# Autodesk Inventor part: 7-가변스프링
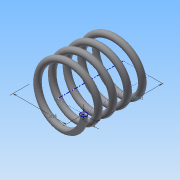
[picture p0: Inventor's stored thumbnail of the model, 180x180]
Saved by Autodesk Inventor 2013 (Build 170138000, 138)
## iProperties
Created: 2015-03
Part Number: 7-가변스프링
Material: 강철, 탄소
Document SubType Name: Modeling
Designer: Administrator
Density: 7.87 g/cm^3
Mass: 47.9946 g
Surface Area: 62.0026 cm^2
Volume: 6.09842 cm^3
Author: Administrator
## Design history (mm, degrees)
sketch "스케치1"
  geometry: L1 (0, 0)-(17.5, 0); L2 (17.5, 0)-(17.5, 43.5); L3 (17.5, 43.5)-(0, 43.5); L4 (0, 43.5)-(0, 0); C1 r 2 at (17.5, 0)
  constraints: 8 end point, 2 parallel, 1 centre point, 1 coincident, 1 horizontal, 1 perpendicular
  dimensions: "d0" = 35 diameter of L2 L4; "d2" = 43.5 distance of L1.end L2.end (derived); "d3" = 4 diameter of C1
feature "코일1" sketch "스케치1" pitch "d4" = 10; turns "d6" = 4.5; dims "d5" = 43.5 (= d2), "d7" = 0, angle "d8" = 90 deg, angle "d9" = 90 deg, "d10" = 0, "d11" = 0
node "작업 평면1"
sketch "스케치2"
  geometry: L1 (15.5, 0)-(19.5, 0) reference; L2 (15.5, 0)-(19.5, 0) reference; 1 further point
  constraints: 2 horizontal alignment
extrude "돌출1" cut sketch "스케치2" stored distance "d13" = 10; taper "d14" = 0 deg
node "작업 평면2"
sketch "스케치3"
  geometry: L1 (15.5, 0)-(19.5, 0) reference; 1 further point
  constraints: 1 horizontal alignment
extrude "돌출2" cut sketch "스케치3" stored distance "d16" = 10; taper "d17" = 0 deg
node "솔리드1"
node "절단 모서리 투영1"
node "절단 모서리 투영2"
node "절단 모서리 투영3"
other parameters: "d12" = 0, "d15" = -43.5 (= -d2)
